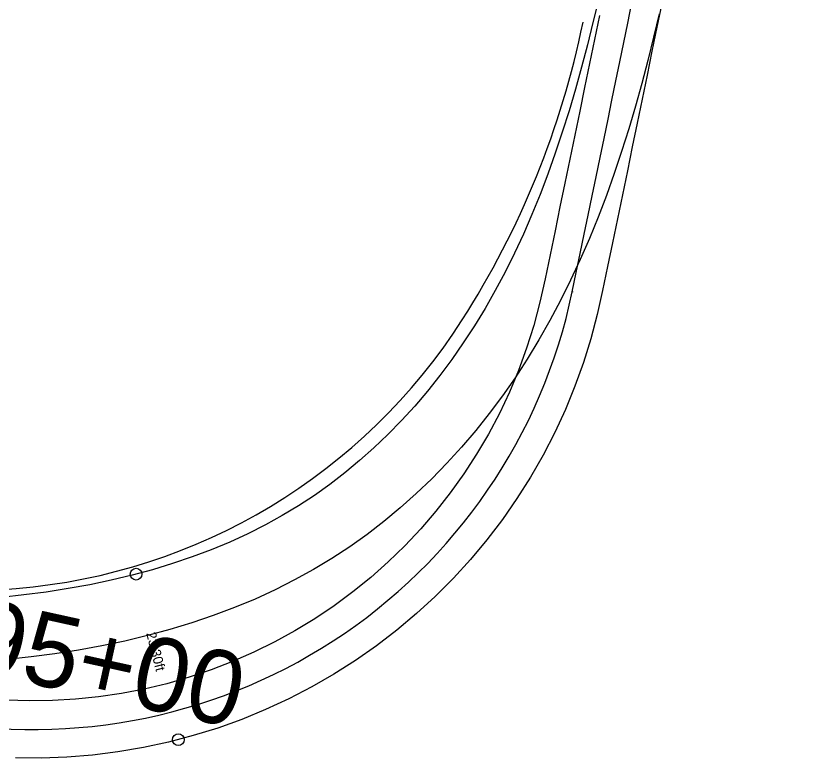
# Model space of a CAD drawing. Extents: x -69 to 14108008, y -6 to 8640172.
# Drawn here: x 14107764 to 14107873.2, y 8639454 to 8639555.2 of the extents above; entities that cross this region are included whole.
import ezdxf

# ---------------------------------------------------------------- set-up
doc = ezdxf.new("R2010")
doc.units = 0
for name, color, linetype in [('Alignment', 7, 'Continuous'), ('AutoTurn', 7, 'Continuous'), ('AutoTurn1', 7, 'Continuous'), ('TextAlignmentLrg', 7, 'Continuous'), ('TextAlignmentSml', 7, 'Continuous')]:
    doc.layers.add(name, color=color, linetype=linetype)

msp = doc.modelspace()

# ---------------------------------------------------------------- linework, layer by layer
at = {"layer": 'Alignment'}
for centre, radius, start, end in [((14107723.69, 8639578.39), 120, 327.4099, 348.4493), ((14107757.39, 8639556.85), 80, 274.7091, 327.4099), ((14107757.39, 8639556.85), 80, 274.7091, 327.4099), ((14107737.69, 8639796.04), 320, 257.6983, 274.7091), ((14107737.69, 8639796.04), 320, 257.6983, 274.7091)]:
    msp.add_arc(centre, radius, start, end, dxfattribs=at)
at = {"layer": 'AutoTurn'}
for centre, radius, start, end in [((14098576.76, 8641447.78), 9462, 348.22936, 349.264447), ((14107766.37, 8639532.88), 75, 257.6983, 348.2294)]:
    msp.add_arc(centre, radius, start, end, dxfattribs=at)
at = {"layer": 'AutoTurn1'}
for points in [[(14107843.35, 8639557.43), (14107842.61, 8639554.33), (14107841.85, 8639551.26), (14107841.05, 8639548.22), (14107840.22, 8639545.22), (14107839.35, 8639542.26), (14107838.43, 8639539.35), (14107837.47, 8639536.48), (14107836.46, 8639533.65), (14107835.4, 8639530.87), (14107834.29, 8639528.14), (14107833.13, 8639525.46), (14107831.91, 8639522.84), (14107830.63, 8639520.27), (14107829.29, 8639517.76), (14107827.9, 8639515.31), (14107826.44, 8639512.93), (14107824.93, 8639510.6), (14107823.36, 8639508.34), (14107821.74, 8639506.15), (14107820.05, 8639504.03), (14107818.31, 8639501.99), (14107816.51, 8639500.01), (14107814.66, 8639498.11), (14107812.76, 8639496.29), (14107810.8, 8639494.55), (14107808.8, 8639492.89), (14107806.75, 8639491.31), (14107804.65, 8639489.82), (14107802.49, 8639488.4), (14107800.26, 8639487.06), (14107797.95, 8639485.78), (14107795.57, 8639484.58), (14107793.11, 8639483.45), (14107790.58, 8639482.39), (14107787.98, 8639481.41), (14107785.3, 8639480.51), (14107782.57, 8639479.68), (14107779.77, 8639478.92), (14107776.91, 8639478.24), (14107774.01, 8639477.63), (14107771.05, 8639477.1), (14107768.06, 8639476.63), (14107765.02, 8639476.24), (14107761.96, 8639475.9)], [(14107851.99, 8639556.93), (14107851.32, 8639553.67), (14107850.65, 8639550.4), (14107849.99, 8639547.14), (14107849.32, 8639543.87), (14107848.65, 8639540.6), (14107847.97, 8639537.34), (14107847.3, 8639534.07), (14107846.63, 8639530.81), (14107845.95, 8639527.55), (14107845.27, 8639524.28), (14107844.59, 8639521.02), (14107843.92, 8639517.75), (14107843.19, 8639514.47), (14107842.33, 8639511.19), (14107841.31, 8639507.93), (14107840.15, 8639504.71), (14107838.85, 8639501.53), (14107837.4, 8639498.39), (14107835.82, 8639495.32), (14107834.1, 8639492.32), (14107832.24, 8639489.38), (14107830.26, 8639486.53), (14107828.15, 8639483.77), (14107825.92, 8639481.09), (14107823.58, 8639478.52), (14107821.12, 8639476.04), (14107818.55, 8639473.68), (14107815.88, 8639471.43), (14107813.11, 8639469.3), (14107810.25, 8639467.3), (14107807.3, 8639465.42), (14107804.27, 8639463.68), (14107801.16, 8639462.07), (14107797.99, 8639460.59), (14107794.75, 8639459.26), (14107791.46, 8639458.08), (14107788.12, 8639457.04), (14107784.74, 8639456.15), (14107781.32, 8639455.41), (14107777.86, 8639454.83), (14107774.39, 8639454.39), (14107770.9, 8639454.12), (14107767.4, 8639453.99), (14107763.9, 8639454.03)], [(14107843.48, 8639555.26), (14107842.81, 8639551.99), (14107842.15, 8639548.73), (14107841.48, 8639545.47), (14107840.81, 8639542.2), (14107840.13, 8639538.94), (14107839.46, 8639535.68), (14107838.79, 8639532.42), (14107838.11, 8639529.16), (14107837.44, 8639525.89), (14107836.76, 8639522.63), (14107836.08, 8639519.37), (14107835.37, 8639516.16), (14107834.54, 8639513), (14107833.57, 8639509.91), (14107832.46, 8639506.87), (14107831.22, 8639503.9), (14107829.86, 8639501), (14107828.37, 8639498.17), (14107826.75, 8639495.42), (14107825.02, 8639492.74), (14107823.16, 8639490.15), (14107821.2, 8639487.66), (14107819.13, 8639485.25), (14107816.96, 8639482.94), (14107814.68, 8639480.73), (14107812.31, 8639478.63), (14107809.86, 8639476.64), (14107807.31, 8639474.76), (14107804.69, 8639472.99), (14107801.99, 8639471.35), (14107799.22, 8639469.82), (14107796.38, 8639468.42), (14107793.49, 8639467.15), (14107790.55, 8639466.01), (14107787.55, 8639465), (14107784.52, 8639464.13), (14107781.45, 8639463.39), (14107778.35, 8639462.79), (14107775.22, 8639462.33), (14107772.08, 8639462), (14107768.93, 8639461.82), (14107765.78, 8639461.78), (14107762.62, 8639461.87)], [(14107851.63, 8639555.51), (14107850.87, 8639552.32), (14107850.08, 8639549.15), (14107849.26, 8639546.01), (14107848.39, 8639542.89), (14107847.48, 8639539.8), (14107846.52, 8639536.74), (14107845.51, 8639533.71), (14107844.44, 8639530.72), (14107843.32, 8639527.76), (14107842.13, 8639524.85), (14107840.88, 8639521.98), (14107839.57, 8639519.16), (14107838.19, 8639516.39), (14107836.74, 8639513.68), (14107835.23, 8639511.01), (14107833.65, 8639508.41), (14107831.99, 8639505.87), (14107830.27, 8639503.4), (14107828.48, 8639500.99), (14107826.63, 8639498.65), (14107824.7, 8639496.38), (14107822.71, 8639494.19), (14107820.65, 8639492.08), (14107818.53, 8639490.06), (14107816.35, 8639488.11), (14107814.11, 8639486.26), (14107811.81, 8639484.49), (14107809.46, 8639482.81), (14107807.03, 8639481.22), (14107804.53, 8639479.71), (14107801.94, 8639478.28), (14107799.28, 8639476.93), (14107796.54, 8639475.67), (14107793.73, 8639474.5), (14107790.85, 8639473.41), (14107787.91, 8639472.42), (14107784.92, 8639471.51), (14107781.87, 8639470.69), (14107778.78, 8639469.95), (14107775.64, 8639469.29), (14107772.47, 8639468.72), (14107769.27, 8639468.22), (14107766.04, 8639467.8), (14107762.79, 8639467.44)]]:
    msp.add_lwpolyline(points, dxfattribs=at)
for centre, radius in [((14107839.79, 8639517.58), 0.0417), ((14107839.79, 8639517.58), 0.0417), ((14107780.33, 8639479.07), 0.8), ((14107786.09, 8639456.49), 0.8)]:
    msp.add_circle(centre, radius, dxfattribs=at)
for centre, radius, start, end in [((14098576.76, 8641447.78), 9462, 348.22936, 349.264447), ((14107766.37, 8639532.88), 75, 257.6983, 348.2294)]:
    msp.add_arc(centre, radius, start, end, dxfattribs=at)

# ---------------------------------------------------------------- texts
msp.add_text('23.30ft', height=1.333, rotation=284.3178, dxfattribs=at).set_placement((14107781.7, 8639471))
at = {"layer": 'TextAlignmentLrg'}
msp.add_text('10295+00', height=10.02, rotation=347.6032, dxfattribs=at).set_placement((14107735.18, 8639470.92))
at = {"layer": 'TextAlignmentSml'}
msp.add_text('10295+00', height=10.02, rotation=347.6032, dxfattribs=at).set_placement((14107735.18, 8639470.92))

doc.saveas('drawing.dxf')
